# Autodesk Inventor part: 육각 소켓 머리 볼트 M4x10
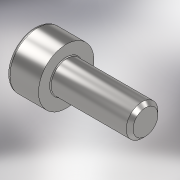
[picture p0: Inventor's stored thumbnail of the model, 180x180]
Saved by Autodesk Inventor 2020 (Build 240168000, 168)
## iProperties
Created: 2024-11
Part Number: 육각 소켓 머리 볼트 M4x10
Material: 강철, 연강
Description: 6각머리 태핑 나사
Document SubType Name: Modeling
Designer: 1강의실14
Density: 7.85 g/cm^3
Appearance: 기본값
Author: jhkim
Sending System: Autodesk Inventor 2025
Preprocessor: ST-DEVELOPER v20
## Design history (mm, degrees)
feature "Solid1"
node "솔리드1"
